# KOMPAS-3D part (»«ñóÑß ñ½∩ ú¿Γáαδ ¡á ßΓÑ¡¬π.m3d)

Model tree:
1. Эскиз:1
2. Операция выдавливания:1
     Расстояние 1 = 40
3. Эскиз:2
4. Операция выдавливания:2
     Расстояние 1 = 4
5. Эскиз:3
6. Операция выдавливания:3
     Расстояние 1 = 70
7. Эскиз:4
8. Операция выдавливания:4
     Расстояние 1 = 6
9. Эскиз:5
10. Вырезать элемент выдавливания:1
     Расстояние 1 = 10
11. Эскиз:6
12. Вырезать элемент выдавливания:2
     Расстояние 1 = 3; Угол 1 = 30
13. Скругление:1
     Радиус = 11
14. Скругление:2
     Радиус = 13
15. Скругление:3
     Радиус = 4
16. Скругление:4
     Радиус = 4
17. Скругление:5
     Радиус = 4
